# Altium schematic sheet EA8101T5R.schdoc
size 127 x 101 mm
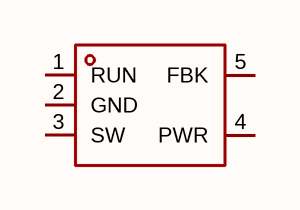
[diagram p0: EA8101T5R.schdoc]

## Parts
U?  ea8101t5r  [SOT-23-5_L2.9-W1.6-P0.95-LS2.9-BL]  (value not drawn)

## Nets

Not connected (* = marked no-connect by the designer): U? 1(RUN) 2(GND) 3(SW) 4(PWR) 5(FBK)

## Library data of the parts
U? = ea8101t5r: 功能类型:降压型;工作电压:2.5V~5.5V;输出电压:600mV~5.5V;输出电流:1A;输出类型:可调;; Manufacturer: everanalog(申风); AddInBom: yes; ModelId: f208335ea6894ff1b04bfab971ca745a; ModelTransform: 114.173,114.173,0,0,0,0,0,-0.003,0; Function: 降压型; Output Current: 1A; Frequency - Switching: 1.5MHz; Synchronous Rectifier: 是; Number of Outputs: 1; Topology: 降压式; Quiescent Current: 45uA; Switch tube (built-in/external): 内置; Output Type: 可调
